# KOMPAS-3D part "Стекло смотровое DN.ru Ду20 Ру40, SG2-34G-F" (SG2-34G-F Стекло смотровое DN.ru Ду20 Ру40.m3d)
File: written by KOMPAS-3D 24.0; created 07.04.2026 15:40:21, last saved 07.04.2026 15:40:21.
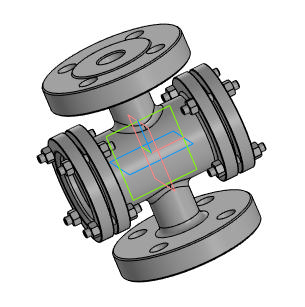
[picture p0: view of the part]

Document properties: Автор: Main; Полное имя файла: D:\DN.ru Аутсерс\Стекло смотровое DN.ru\Исходники\Стекло смотровое DN.ru SG2-34G-F тип В ГОСТ 21836-2021 Ду20 Ру40, углеродистая сталь, фланцевое\SG2-34G-F Стекло смотровое DN.ru Ду20 Ру40.m3d

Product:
- Part/product: Стекло смотровое DN.ru Ду20 Ру40  | designation SG2-34G-F
    Масса: 4.8
    Раздел спецификации: Прочие изделия
    Примечание: D500-00080

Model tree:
1. Операция без истории:1

Expressions: SG2-34G-F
